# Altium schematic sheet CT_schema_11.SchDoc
size 281 x 153 mm
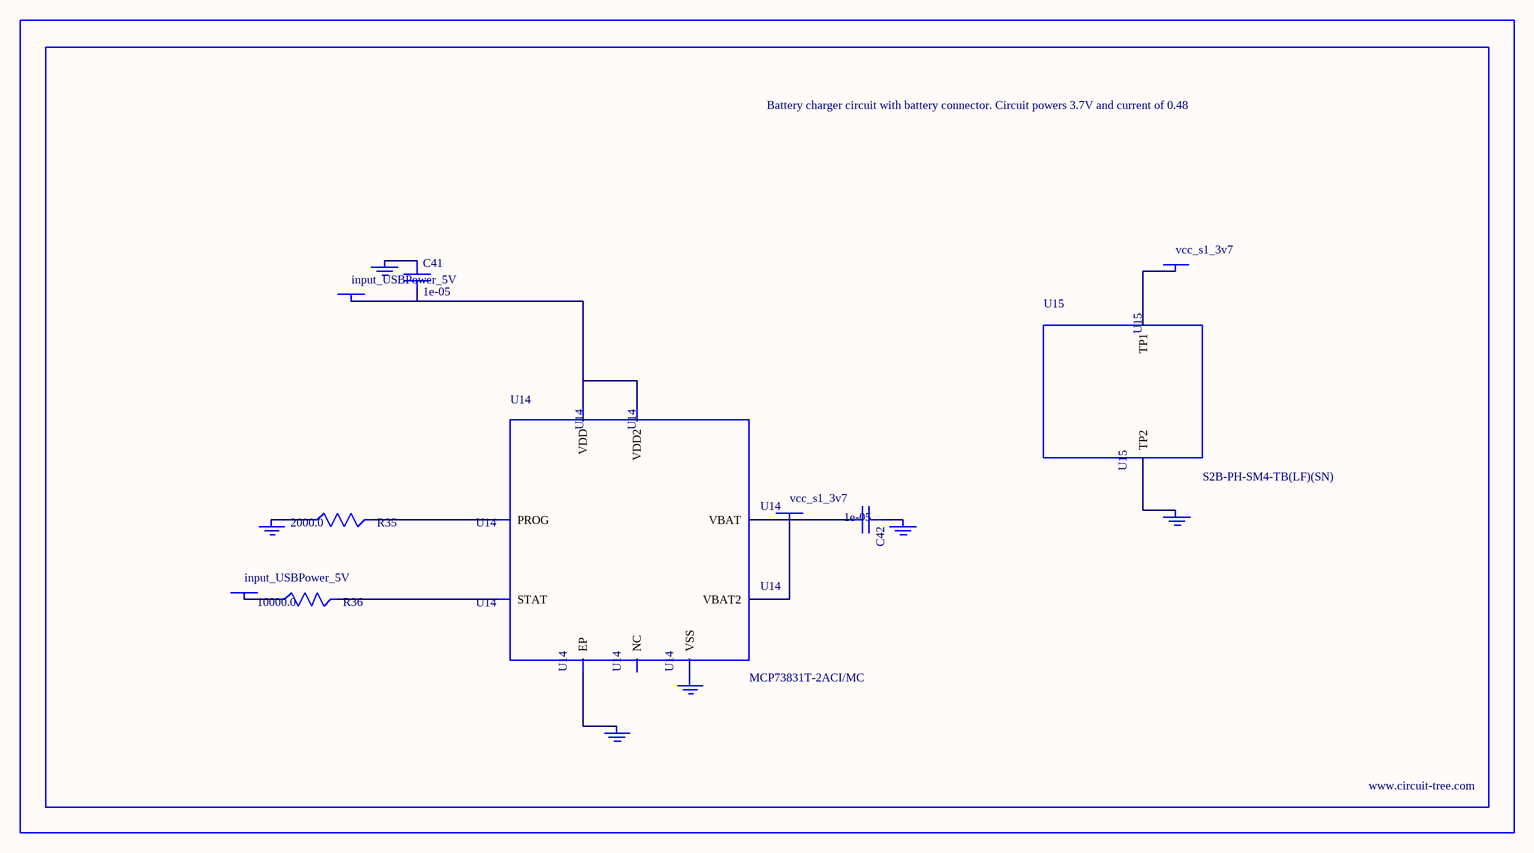
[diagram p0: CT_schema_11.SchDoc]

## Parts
BORDER10  (no value)
C41  1e-05  [C1206]
C42  1e-05  [C1206]
GND_INSTANCE_10_0  (no value)
GND_INSTANCE_10_1  (no value)
GND_INSTANCE_10_2  (no value)
GND_INSTANCE_10_3  (no value)
GND_INSTANCE_10_4  (no value)
GND_INSTANCE_10_5  (no value)
POWER_INSTANCE_10_0  input_USBPower_5V
POWER_INSTANCE_10_1  input_USBPower_5V
POWER_INSTANCE_10_2  vcc_s1_3v7
POWER_INSTANCE_10_3  vcc_s1_3v7
R35  2000.0  [R0603]
R36  10000.0  [R0603]
U14  MCP73831T-2ACI/MC  [DFN8_2X3MC]
U15  S2B-PH-SM4-TB(LF)(SN)  [JST-2-SMD]

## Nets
NetC41_1: C41.1 GND_INSTANCE_10_0.0(GND)
NetC41_2: C41.2 POWER_INSTANCE_10_0.0(PWR) U14.1(VDD) U14.2(VDD2)
NetC42_1: C42.1 GND_INSTANCE_10_1.0(GND)
NetC42_2: C42.2 POWER_INSTANCE_10_2.0(PWR) U14.3(VBAT) U14.4(VBAT2)
NetGND_INSTANCE_10_2_0: GND_INSTANCE_10_2.0(GND) R35.1
NetGND_INSTANCE_10_3_0: GND_INSTANCE_10_3.0(GND) U14.9(EP)
NetGND_INSTANCE_10_4_0: GND_INSTANCE_10_4.0(GND) U14.6(VSS)
NetGND_INSTANCE_10_5_0: GND_INSTANCE_10_5.0(GND) U15.2(TP2)
NetPOWER_INSTANCE_10_1_0: POWER_INSTANCE_10_1.0(PWR) R36.1
NetPOWER_INSTANCE_10_3_0: POWER_INSTANCE_10_3.0(PWR) U15.1(TP1)
NetR35_2: R35.2 U14.8(PROG)
NetR36_2: R36.2 U14.5(STAT)

Not connected (* = marked no-connect by the designer): U14 7(NC)

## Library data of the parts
BORDER10 = BORDER_PAGE10
C41 C42 = C1206C106K3RACTU
GND_INSTANCE_10_0-GND_INSTANCE_10_5 = GND
POWER_INSTANCE_10_0-POWER_INSTANCE_10_3 = PWR
R35 = RC0603JR-072KL
R36 = RC0603JR-0710KL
